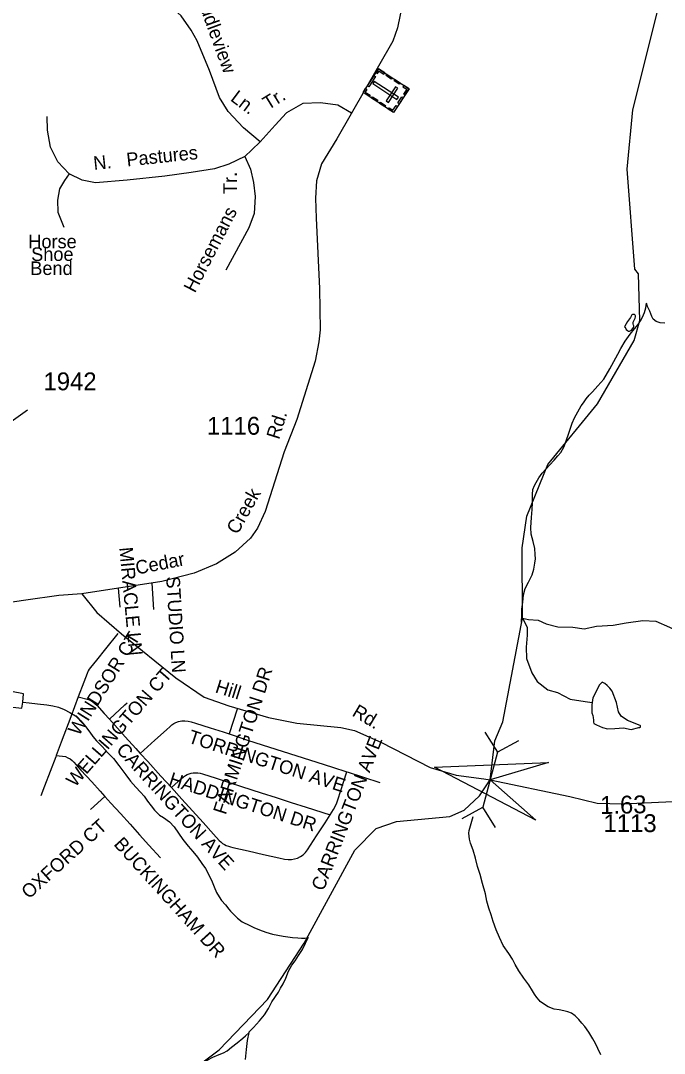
# Model space of a CAD drawing. Extents: x 2126262 to 2293712, y 749403 to 919119.
# Drawn here: x 2164263 to 2168767, y 831672 to 838902 of the extents above; entities that cross this region are included whole.
import ezdxf

# ---------------------------------------------------------------- set-up
doc = ezdxf.new("R2010")
doc.units = 0
for name, color, linetype in [('Exist Cultural Cemetery CELL', 7, 'Continuous'), ('Exist Hydrographic Creek Single Shore', 7, 'Continuous'), ('Exist Hydrographic Misc Water Feature', 7, 'Continuous'), ('Exist Hydrographic Pond Under 1500 Sq Ft', 7, 'Continuous'), ('Exist Road Non-System Type 51', 7, 'Continuous'), ('Exist Road Non-System Type 51 Label', 7, 'Continuous'), ('Exist Road Secondary Mileage Hundredths English Label', 7, 'Continuous'), ('Exist Road Secondary Structure Pipe Attributed CELL', 7, 'Continuous'), ('Exist Road Secondary Structure Pipe CELL', 7, 'Continuous'), ('Exist Road Secondary Type 51 Attributed', 7, 'Continuous'), ('Exist Road Secondary Type 51 Label', 7, 'Continuous'), ('Exist Road Secondary Type 51 Number Label', 7, 'Continuous')]:
    doc.layers.add(name, color=color, linetype=linetype)

msp = doc.modelspace()

# ---------------------------------------------------------------- linework, layer by layer
at = {"layer": 'Exist Cultural Cemetery CELL'}
for points in [[(2166980.9, 838425.1), (2166871.6, 838258.7), (2166658.7, 838398.5), (2166768, 838564.9)], [(2166746.1, 838510.6), (2166699.5, 838439.6), (2166690, 838445.9), (2166736.6, 838516.8)], [(2166749.9, 838537.2), (2166759.5, 838530.9), (2166771.6, 838549.3), (2166805.4, 838527.1), (2166811.5, 838536.4), (2166768.1, 838564.9)], [(2166826.5, 838526.5), (2166862.7, 838502.8), (2166856.5, 838493.2), (2166820.3, 838517)], [(2166676.9, 838426.2), (2166686.5, 838419.9), (2166674.5, 838401.5), (2166708.2, 838379.3), (2166702.1, 838370), (2166658.7, 838398.5)], [(2166896.5, 838350.1), (2166906.8, 838365.7), (2166737.3, 838477), (2166727, 838461.4)], [(2166901.6, 838428.4), (2166886, 838438.6), (2166821.3, 838340.2), (2166836.9, 838329.9)], [(2166882.7, 838489.6), (2166918.9, 838465.8), (2166912.6, 838456.3), (2166876.4, 838480.1)], [(2166944.7, 838448.9), (2166938.4, 838439.4), (2166965.3, 838421.7), (2166943.1, 838387.8), (2166952.4, 838381.7), (2166980.9, 838425.1)], [(2166725.4, 838368.3), (2166761.6, 838344.5), (2166755.3, 838335), (2166719.1, 838358.8)], [(2166940.2, 838363.2), (2166911.7, 838319.9), (2166902.2, 838326.2), (2166930.7, 838369.5)], [(2166780.5, 838332.1), (2166816.7, 838308.3), (2166810.4, 838298.8), (2166774.2, 838322.6)], [(2166835.3, 838282.5), (2166841.5, 838291.9), (2166868.4, 838274.3), (2166890.7, 838308.2), (2166900, 838302.1), (2166871.5, 838258.7)]]:
    msp.add_lwpolyline(points, close=True, dxfattribs=at)
at = {"layer": 'Exist Hydrographic Creek Single Shore'}
msp.add_lwpolyline([(2167775.4, 834718), (2167772.4, 835210.2), (2167804.4, 835432.6), (2167952.4, 835793.7), (2168300.4, 836219.6), (2168555.5, 836663.8), (2168596.5, 836803.9), (2168586.4, 837129), (2168561.4, 837162.3), (2168507.5, 837862.2), (2168546.4, 838278), (2168986.5, 840030.6), (2169077.5, 840205.9), (2169342.4, 840515.4), (2169416.5, 840651.6), (2169572.5, 841058.5), (2169626.4, 841818.5), (2169607.4, 842274.9), (2169586.5, 843082.3), (2169729.4, 844234.2)], dxfattribs=at)
at = {"layer": 'Exist Hydrographic Misc Water Feature'}
for points in [[(2167767.4, 834690.3), (2167767.4, 834694.3), (2167769, 834736.4), (2167770.8, 834782.4), (2167776.6, 834830.4), (2167782.3, 834882.4), (2167794, 834926.5), (2167815.8, 834970.6), (2167841.6, 835022.7), (2167853.3, 835062.8), (2167861.1, 835104.8), (2167864.8, 835134.8), (2167864.6, 835164.8), (2167860.2, 835206.8), (2167850, 835256.7), (2167835.8, 835306.6), (2167833.6, 835352.6), (2167837.1, 835422.6), (2167842.8, 835480.6), (2167844.7, 835528.6), (2167844.3, 835584.6), (2167848.1, 835620.6), (2167857.8, 835646.6), (2167869.9, 835668.7), (2167889.6, 835700.8), (2167913.4, 835732.9), (2167965, 835793.2), (2167996.8, 835825.4), (2168022.9, 835855.5), (2168042.5, 835879.6), (2168066.3, 835919.7), (2168097.9, 836007.9), (2168115.5, 836062), (2168121.3, 836084), (2168139.1, 836122.1), (2168160.9, 836164.2), (2168186.5, 836206.4), (2168200.6, 836226.4), (2168220.3, 836254.5), (2168242.3, 836280.6), (2168264, 836302.8), (2168301.7, 836345), (2168343.6, 836393.2), (2168387, 836463.4), (2168412.9, 836515.6), (2168442.6, 836567.7), (2168462.3, 836605.8), (2168494.1, 836658), (2168527.9, 836706.2), (2168557.6, 836744.3), (2168583.3, 836774.4), (2168601.3, 836800.5), (2168615, 836826.6), (2168628.8, 836858.7), (2168636.8, 836890.7), (2168642.5, 836924.7)], [(2168771.3, 836783.5), (2168737.3, 836785.3), (2168709.4, 836795.2), (2168689.1, 836813), (2168681.1, 836830.9), (2168664.9, 836868.9), (2168650.5, 836900.8), (2168642.5, 836924.7)], [(2164746.4, 831066.9), (2165095.4, 831279.5), (2165651.5, 831697.8), (2165990.5, 832048.4), (2166247.4, 832443.3), (2166601.5, 833095.4), (2166750.4, 833246.5), (2166892.5, 833296.1), (2167266.5, 833331), (2167366.4, 833374.9), (2167474.4, 833474.3), (2167548.7, 833587.9), (2167580.4, 833859.3), (2167637.4, 833992.6), (2167775.4, 834718)], [(2167775.4, 834718), (2167808.4, 834654.7), (2167808.4, 834599), (2167799.4, 834516.3), (2167803, 834435.4), (2167840.7, 834336.5), (2167878.4, 834275.4), (2167952.1, 834217.8), (2168018.6, 834198.1), (2168108.4, 834151.3), (2168214.4, 834135.1), (2168262.6, 834129.5)], [(2167775.4, 834718), (2167817.4, 834710.4), (2167885.6, 834705), (2167939.5, 834679.8), (2168022.2, 834658.3), (2168128.2, 834654.7), (2168205.4, 834643.9), (2168291.7, 834663.7), (2168410.2, 834669.1), (2168500.1, 834685.2), (2168616.8, 834703.2), (2168708.5, 834697.8), (2168803.7, 834654.7), (2168907.9, 834606.1), (2169001.3, 834561.2), (2169085.8, 834528.8), (2169155.8, 834518.1), (2169182.8, 834480.3), (2169225.9, 834422.8), (2169252.6, 834382.6)], [(2164277.6, 834130.9), (2164283.1, 834188.8), (2164199, 834206.3), (2164139, 834222), (2164118.9, 834231.9), (2164098.8, 834251.8), (2164074.6, 834283.7), (2164060.6, 834301.6), (2164054.5, 834307.5), (2164050.6, 834309.5), (2164046.5, 834299.5), (2164048.7, 834267.5), (2164052.8, 834237.5), (2164059, 834209.6), (2164065.3, 834183.6), (2164077.2, 834143.7), (2164081.5, 834115.7), (2164085.6, 834107.8), (2164099.6, 834101.8), (2164127.5, 834099.9), (2164157.6, 834098.2), (2164187.6, 834098.4), (2164271.6, 834088.8), (2164277.6, 834130.9)], [(2164277.6, 834130.9), (2164321.7, 834127.1), (2164381.5, 834119.4), (2164445.5, 834111.8), (2164487.6, 834106), (2164527.5, 834096.3), (2164567.5, 834080.5), (2164605.9, 834058.7), (2164645.9, 834034.9), (2164684, 833999.2), (2164716.4, 833959.3), (2164746.5, 833921.6), (2164768.5, 833889.7), (2164792.9, 833859.8), (2164808.9, 833843.9), (2164833.1, 833820), (2164875.3, 833774.3), (2164911.6, 833736.5), (2164949.7, 833686.7), (2164978, 833650.9), (2164998.1, 833623), (2165032.4, 833577.2), (2165068.5, 833535.4), (2165100.9, 833501.7), (2165126.9, 833471.8), (2165151.1, 833438), (2165175.3, 833404.1), (2165199.5, 833374.2), (2165233.5, 833340.5), (2165261.8, 833322.6), (2165303.9, 833292.9), (2165336.1, 833257), (2165368.2, 833213.2), (2165398.6, 833169.4), (2165434.9, 833121.6), (2165467.1, 833085.9), (2165501.3, 833046), (2165531.5, 833002.2), (2165555.5, 832966.3), (2165584, 832912.5), (2165604.1, 832872.7), (2165616.4, 832838.7), (2165632.6, 832798.8), (2165650.8, 832769), (2165668.9, 832743.1), (2165697.2, 832711.2), (2165719.3, 832681.3), (2165731.4, 832667.5), (2165779.6, 832617.7), (2165813.8, 832591.9), (2165865.9, 832566.2), (2165893.8, 832554.4), (2165934, 832536.6), (2165978.1, 832520.8), (2166026.1, 832507.2), (2166100.3, 832493.6), (2166164.3, 832483.9), (2166202.4, 832480.1), (2166228.2, 832478.3), (2166250.4, 832478.4), (2166272.3, 832482.5), (2166278.3, 832484.6)], [(2168322.2, 831662.3), (2168302.1, 831706.2), (2168285.7, 831742.1), (2168267.5, 831774), (2168239.4, 831819.9), (2168211.1, 831859.6), (2168191, 831883.5), (2168168.9, 831909.4), (2168142.8, 831935.3), (2168118.6, 831953.1), (2168092.6, 831963), (2168064.5, 831970.8), (2168030.6, 831976.6), (2167996.6, 831982.4), (2167954.6, 831998.2), (2167922.4, 832017.9), (2167898.4, 832035.8), (2167890.4, 832043.8), (2167874, 832063.7), (2167858, 832085.6), (2167845.9, 832109.6), (2167819.6, 832151.3), (2167783.4, 832199.2), (2167749.1, 832249), (2167722.9, 832294.8), (2167704.6, 832330.7), (2167678.6, 832370.5), (2167640, 832426.3), (2167613.8, 832484.1), (2167591.6, 832538), (2167569.3, 832595.8), (2167555.1, 832641.7), (2167538.7, 832687.6), (2167526.2, 832737.5), (2167516, 832789.5), (2167495.9, 832861.3), (2167479.3, 832923.2), (2167461, 832981.1), (2167444.8, 833039.1), (2167428.4, 833094.9), (2167412, 833142.8), (2167404, 833170.7), (2167399.9, 833212.7), (2167401.5, 833232.7), (2167419.4, 833298.8), (2167429, 833330.8)], [(2165862, 831822.4), (2165891.7, 831852.6), (2165933.6, 831898.8), (2165969.3, 831943), (2165997.1, 831985.1), (2166020.7, 832033.2), (2166066.2, 832101.5), (2166082.2, 832127.6), (2166100.1, 832159.6), (2166117.7, 832199.7), (2166137.6, 832247.8), (2166161.4, 832290), (2166183.1, 832320.1), (2166206.9, 832358.2), (2166234.6, 832400.3), (2166256.3, 832444.5), (2166278.3, 832484.6)], [(2165459.9, 831526.2), (2165467.9, 831536.3), (2165485.5, 831556.3), (2165509.5, 831580.5), (2165549.3, 831612.7), (2165573.3, 831626.8), (2165607.1, 831645), (2165651, 831665.3), (2165682.8, 831675.4), (2165706.8, 831689.6), (2165738.6, 831715.7), (2165778.6, 831745.9), (2165818.3, 831778.1), (2165836.4, 831794.3), (2165861.1, 831817.8), (2165862, 831822.4)], [(2165835.2, 831628.2), (2165842.7, 831700.3), (2165850.3, 831762.4), (2165861.1, 831817.8), (2165862, 831822.4)]]:
    msp.add_lwpolyline(points, dxfattribs=at)
at = {"layer": 'Exist Hydrographic Pond Under 1500 Sq Ft'}
for points in [[(2168562.8, 836819.8), (2168565.5, 836827.7), (2168565.8, 836834.4), (2168563.7, 836840.7), (2168558.8, 836843.8), (2168552, 836845.1), (2168545.5, 836845.6), (2168540, 836842.5), (2168530.3, 836824.3), (2168508.7, 836795.3), (2168490.3, 836762.2), (2168489.8, 836759.4), (2168491.3, 836755.4), (2168497, 836747.4), (2168501.2, 836739.6), (2168509.3, 836733), (2168517.3, 836729.1), (2168524.3, 836729.1), (2168536.6, 836735.4), (2168546.8, 836746.6), (2168552.5, 836753.1), (2168553.8, 836758.8), (2168553.8, 836764.3), (2168550.9, 836769.5), (2168550.2, 836780.2), (2168549.4, 836792.2), (2168562.8, 836819.8)], [(2168403.2, 834208.2), (2168385, 834229), (2168368.4, 834247.1), (2168350.3, 834262), (2168338, 834269.4), (2168333.8, 834269.9), (2168330.1, 834268), (2168314, 834252.1), (2168268.1, 834161.7), (2168259.5, 834111.7), (2168259.5, 834055.5), (2168267.1, 834036.7), (2168268.9, 834023.4), (2168271.1, 834004.3), (2168270.7, 833991.4), (2168274.4, 833981.2), (2168293.5, 833971.6), (2168333.8, 833953.1), (2168370.1, 833944.9), (2168421.3, 833946.5), (2168480.7, 833951.5), (2168534.2, 833939.4), (2168587.8, 833953.6), (2168595.9, 833953.7), (2168599.6, 833954.8), (2168600.2, 833964.1), (2168597.9, 833968), (2168508.8, 834002.7), (2168464.2, 834032.4), (2168447.7, 834063.8), (2168432.8, 834127.9), (2168403.2, 834208.2)]]:
    msp.add_lwpolyline(points, dxfattribs=at)
at = {"layer": 'Exist Road Non-System Type 51'}
for p, q in [((2165181.4, 834963.6), (2165192.5, 834780.6)), ((2164945.4, 834929), (2164957.7, 834795.5)), ((2165776.9, 834082.4), (2165720.9, 833908.6)), ((2164852.7, 833470), (2164752.3, 833378.9))]:
    msp.add_line(p, q, dxfattribs=at)
for points in [[(2165938.3, 838054.2), (2165822.5, 838151.9), (2165715.1, 838266.4), (2165654.4, 838363.5), (2165584.6, 838552), (2165498.2, 838760.8), (2165456.4, 838836.2), (2165385.2, 838936.7), (2165246.4, 839063.1), (2164992.5, 839232)], [(2166578.9, 838255.3), (2166483.1, 838310.4), (2166360.3, 838327.2), (2166237.5, 838321.6), (2166123.1, 838257.4), (2166045, 838170.8), (2165938.3, 838054.2)], [(2164601.8, 837830.1), (2164522.3, 837912.5), (2164472.3, 838016.4), (2164449.9, 838136.4), (2164447.2, 838230)], [(2165938.3, 838054.2), (2165881.1, 837996.9), (2165832.3, 837950.9)], [(2165832.3, 837950.9), (2165720, 837897.8), (2165619.6, 837865.7), (2165456.4, 837837.8), (2165270.8, 837814.1), (2165007.8, 837785.4), (2164786, 837767.3), (2164693.9, 837785.4), (2164601.8, 837830.1)], [(2165832.3, 837950.9), (2165872.1, 837861.5), (2165891.6, 837768), (2165902.8, 837670.2), (2165895.8, 837552.9), (2165858.9, 837451.7), (2165698.4, 837155.7)], [(2164601.8, 837830.1), (2164568.4, 837784), (2164534.9, 837725.4), (2164520.9, 837644.4), (2164523.7, 837562), (2164565.6, 837455.9)], [(2164943.2, 834612.6), (2164856.2, 834503.9), (2164793.7, 834425.9), (2164751.5, 834373.2), (2164743, 834361.7), (2164736.1, 834349.8), (2164728.1, 834331.8), (2164705.3, 834271.5), (2164666.2, 834168.6)], [(2164666.2, 834168.6), (2164613.2, 834028.3), (2164546.8, 833851.7), (2164510.7, 833756.9)], [(2164666.2, 834168.6), (2164737.5, 834148.4), (2164753.3, 834141.5), (2164768.5, 834132.3), (2164782.8, 834121.4), (2164795.7, 834108.8), (2164847.4, 834051.7), (2164883.5, 834011.9)], [(2164883.5, 834011.9), (2164992.8, 834111), (2165008.8, 834125.4)], [(2164883.5, 834011.9), (2164921.2, 833970.2), (2164995.1, 833888.7), (2165069.1, 833807.2), (2165100.2, 833772.5)], [(2165100.2, 833772.5), (2165201.3, 833863.8), (2165282.7, 833937.7), (2165309, 833961.4), (2165321.5, 833971.7), (2165335, 833980.4), (2165349.2, 833987.6), (2165368.5, 833994.5), (2165390, 833999), (2165411.9, 834000.3), (2165434.3, 833998.2), (2165455.8, 833993.1), (2165485.5, 833983.4), (2165589.3, 833950.1), (2165679.5, 833922), (2165720.9, 833908.6)], [(2165720.9, 833908.6), (2165755.8, 833897.5), (2165850.9, 833865.9), (2165952.6, 833833.2), (2166049.2, 833802.1), (2166144.2, 833771.6), (2166239.5, 833741), (2166334.7, 833710.4), (2166444.2, 833675.1), (2166545, 833642.7)], [(2164510.7, 833756.9), (2164507.9, 833748.8), (2164469.1, 833646), (2164429.9, 833543), (2164404.3, 833474.9)], [(2164510.7, 833756.9), (2164577.2, 833749.4), (2164593.8, 833742.1), (2164608.7, 833733.1), (2164623.1, 833722.1), (2164635.6, 833709.8), (2164684.8, 833655.2), (2164760.1, 833572.2), (2164818.9, 833507), (2164852.7, 833470)], [(2165100.2, 833772.5), (2165152.9, 833714.5), (2165244, 833613.9), (2165317.2, 833533.1)], [(2165317.2, 833533.1), (2165388.3, 833597.5), (2165402.1, 833608.5), (2165416.2, 833617.6), (2165428.9, 833623.9), (2165442.1, 833628.7), (2165456, 833632.7), (2165469.3, 833635), (2165485.9, 833636.4), (2165502.1, 833635.8), (2165519.2, 833633.3), (2165535.6, 833629), (2165631.3, 833598.2), (2165722.6, 833568.8), (2165808.3, 833541.2), (2165946.3, 833496.9), (2166051.1, 833463.2), (2166155.6, 833429.5), (2166260.4, 833395.8), (2166428.2, 833341.9)], [(2166428.2, 833341.9), (2166439.4, 833359.8), (2166451.9, 833380.3), (2166463, 833400.9), (2166474.5, 833426.9), (2166484.6, 833454.1), (2166500.8, 833504.6), (2166545, 833642.7)], [(2166545, 833642.7), (2166553.7, 833640), (2166662.9, 833604.7), (2166775.5, 833568.6)], [(2165317.2, 833533.1), (2165317.8, 833532.4), (2165391.8, 833450.9), (2165465.4, 833369.4), (2165539.5, 833287.9), (2165613.3, 833206.3), (2165652.2, 833163.3), (2165663.5, 833152), (2165675.4, 833142.4), (2165688.3, 833134.2), (2165702.1, 833127.2), (2165716.2, 833121.6), (2165730.6, 833117.7), (2165748.4, 833113.5), (2165855.7, 833089.3), (2165962.9, 833065), (2166070.3, 833040.8), (2166109.7, 833031.9), (2166134.9, 833029), (2166157.3, 833029.3), (2166179.4, 833032.9), (2166200.8, 833039.8), (2166221.1, 833049.8), (2166239.3, 833062.7), (2166255.5, 833078.1), (2166270.1, 833097), (2166334, 833195.6), (2166393.3, 833286.8), (2166428.2, 833341.9)], [(2164852.7, 833470), (2164893.8, 833424.8), (2164960.8, 833350.7), (2165028.1, 833276.6), (2165094.9, 833202.4), (2165160.5, 833130.2), (2165240.5, 833041.9)]]:
    msp.add_lwpolyline(points, dxfattribs=at)
at = {"layer": 'Exist Road Secondary Structure Pipe Attributed CELL'}
msp.add_lwpolyline([(2167867.6, 833304.8), (2167158.3, 833674.7), (2167957.5, 833709.1), (2167548.7, 833587.9)], close=True, dxfattribs=at)
at = {"layer": 'Exist Road Secondary Structure Pipe CELL'}
for p, q in [((2167511.8, 833921.3), (2167599.4, 833779.7)), ((2167745.7, 833859.5), (2167599.4, 833779.7)), ((2167599.4, 833779.7), (2167498, 833396.1)), ((2167351.8, 833316.3), (2167498, 833396.1)), ((2167585.6, 833254.4), (2167498, 833396.1))]:
    msp.add_line(p, q, dxfattribs=at)
at = {"layer": 'Exist Road Secondary Type 51 Attributed'}
for points in [[(2166937.4, 839034.4), (2166899.1, 838850.8), (2166868.4, 838758.7), (2166475.6, 838073.8), (2166368.9, 837899.9), (2166332.6, 837781.3), (2166325.7, 837658.4), (2166329.8, 837518.7), (2166354.3, 837026.5), (2166358.7, 836737.6), (2166350.3, 836652.4), (2166323.8, 836518.3), (2166194.8, 836109.9), (2166106.9, 835883.7), (2165973.7, 835465.5), (2165920.6, 835348.2), (2165870.4, 835279.8), (2165763.7, 835181.4), (2165632.5, 835099), (2165477.7, 835033.4), (2165251.7, 834976.1), (2164691.5, 834890.2)], [(2164691.5, 834890.2), (2164529, 834878.4), (2164298.8, 834844.9), (2163995.4, 834800.9), (2163836.3, 834763.2), (2163719.1, 834717.1), (2163622.9, 834662.6)], [(2164691.5, 834890.2), (2164795.5, 834759), (2164968.5, 834608.2), (2165347.9, 834301), (2165547.4, 834165.6), (2165720.4, 834104.1), (2165996.7, 834023.1), (2166194.8, 833984), (2166504.5, 833953.3), (2166598.7, 833933.1), (2166782.8, 833850.7), (2167128.1, 833672.7), (2167309.5, 833619.6), (2167503.4, 833593.1), (2167548.7, 833587.9), (2168105.4, 833469.5), (2168296.5, 833424.8), (2168473.7, 833419.2), (2168930.6, 833439.5)]]:
    msp.add_lwpolyline(points, dxfattribs=at)
at = {"layer": 'Exist Road Secondary Type 51 Number Label'}
msp.add_lwpolyline([(2163352, 835958.9), (2164164, 836071.5), (2164311.7, 836176.4)], dxfattribs=at)

# ---------------------------------------------------------------- texts
at = {"layer": 'Exist Road Non-System Type 51 Label'}
for s, rotation, p in [('Saddleview', 289.83761, (2165465.1, 839135.5)), ('Ln.', 322.90694, (2165724.8, 838346.4)), ('Tr.', 31.59225, (2165994.1, 838273.8)), ('N.   Pastures', 6.01479, (2164776.3, 837856.6)), ('Tr.', 90, (2165775.6, 837688.3)), ('Horsemans', 62.6728, (2165482.4, 836990.8)), ('MIRACLE LN', 275.24588, (2164952.9, 835212.6)), ('STUDIO LN', 273.53501, (2165280.9, 835009.5)), ('WINDSOR CT', 58.05044, (2164669.5, 833889.1)), ('WELLINGTON CT', 49.01048, (2164643.6, 833530.1)), ('FARMINGTON DR', 72.13556, (2165697.6, 833338)), ('TORRINGTON AVE', 342.10927, (2165428.6, 833849.3)), ('CARRINGTON AVE', 68.76961, (2166382.4, 832803.5)), ('CARRINGTON AVE', 312.21689, (2164926.1, 833793)), ('HADDINGTON DR', 342.2073, (2165293.2, 833552.3)), ('OXFORD CT', 42.15837, (2164320.5, 832748.4)), ('BUCKINGHAM DR', 312.16111, (2164909, 833132.9))]:
    msp.add_text(s, height=95, rotation=rotation, dxfattribs=at).set_placement(p)
for s, p in [('Horse', (2164316.1, 837308.4)), ('Shoe', (2164336.2, 837219.8)), ('Bend', (2164330.1, 837121.3))]:
    msp.add_text(s, height=95, dxfattribs=at).set_placement(p)
at = {"layer": 'Exist Road Secondary Mileage Hundredths English Label'}
msp.add_text('1.63', height=125, rotation=1.03982, dxfattribs=at).set_placement((2168318.4, 833347.7))
at = {"layer": 'Exist Road Secondary Type 51 Label'}
for s, rotation, p in [('Rd.', 72.61191, (2166070.7, 835965.1)), ('Creek', 60.63636, (2165780.3, 835299.2)), ('Cedar', 10.91044, (2165076.1, 835023.8)), ('Hill', 342.58571, (2165618.2, 834200.6)), ('Rd.', 329.23843, (2166575.8, 834039.4))]:
    msp.add_text(s, height=95, rotation=rotation, dxfattribs=at).set_placement(p)
at = {"layer": 'Exist Road Secondary Type 51 Number Label'}
for s, p in [('1942', (2164422.5, 836314.2)), ('1116', (2165566.5, 836003.1)), ('1113', (2168341.8, 833221.4))]:
    msp.add_text(s, height=125, dxfattribs=at).set_placement(p)

doc.saveas('drawing.dxf')
